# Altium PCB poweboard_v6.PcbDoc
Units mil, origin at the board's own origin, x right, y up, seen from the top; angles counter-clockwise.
Board outline 2952.84 x 1968.59 mil, 4 copper layers (Top Layer, Signal Layer 2, Signal Layer 1, Bottom Layer), stack 30.634 mil thick; 37 components, 25 nets, 129 pads, 118 vias.
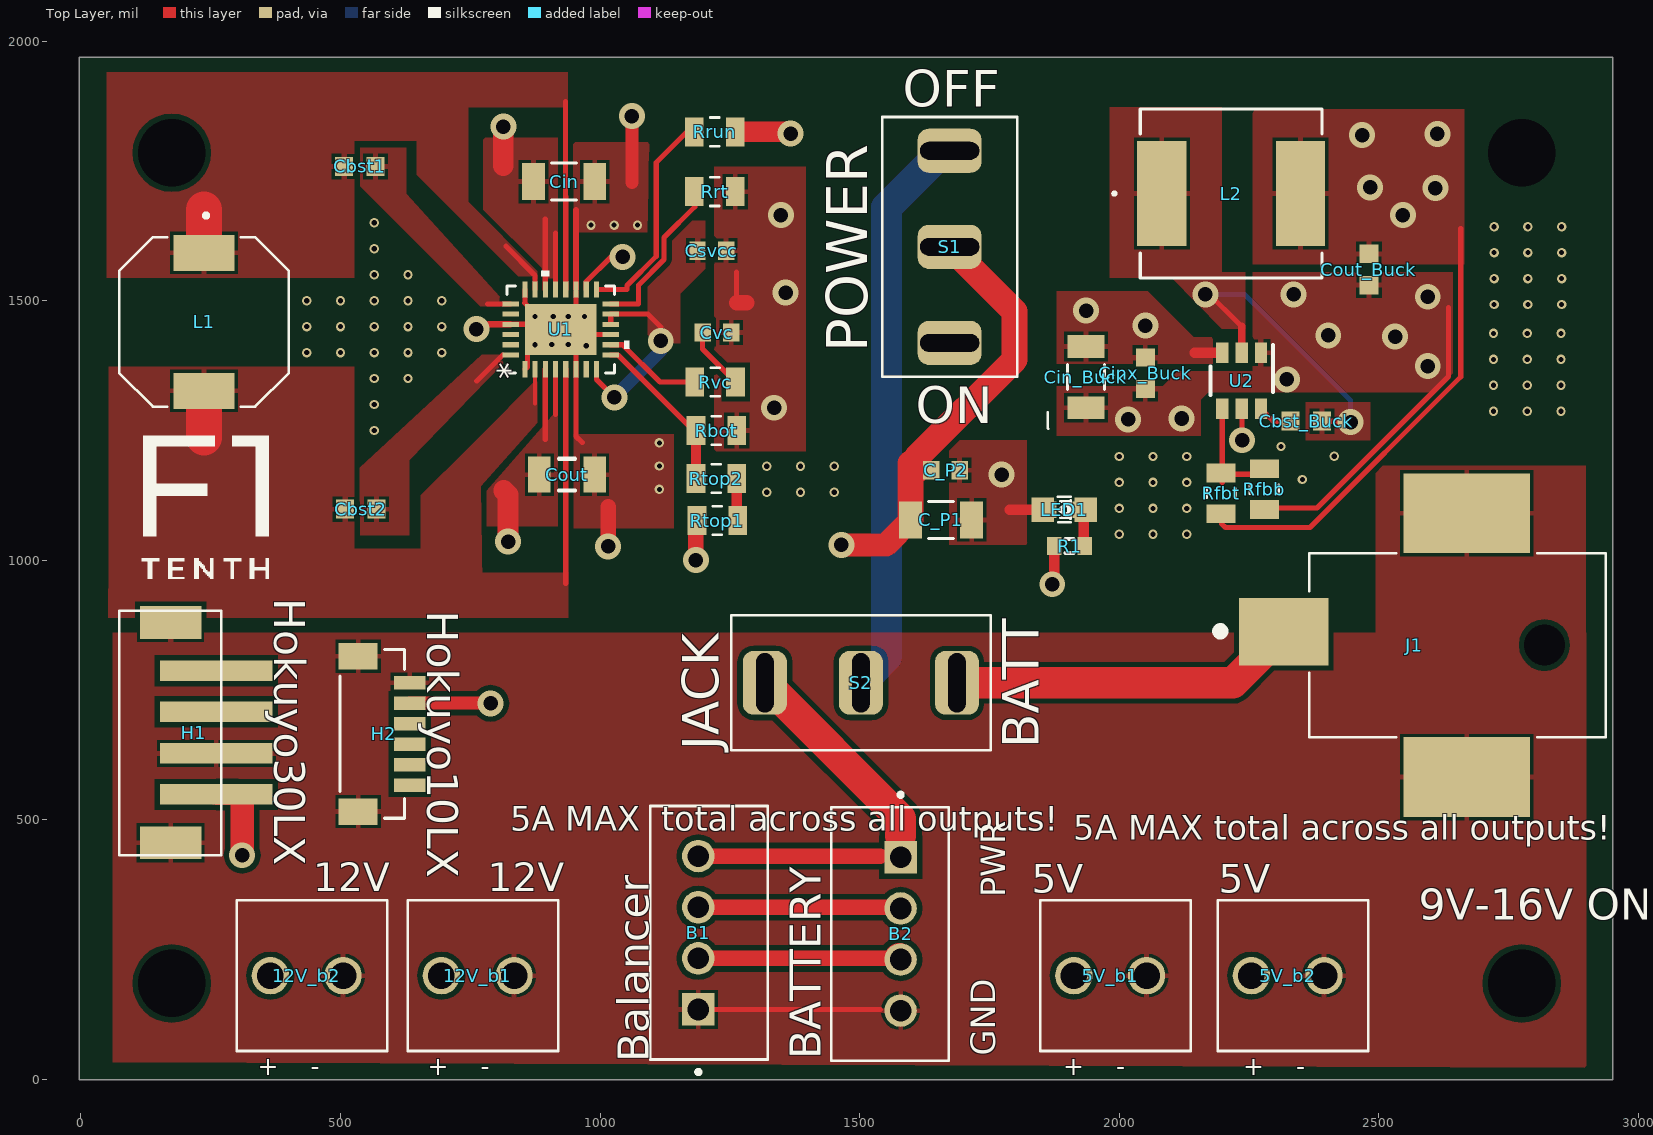
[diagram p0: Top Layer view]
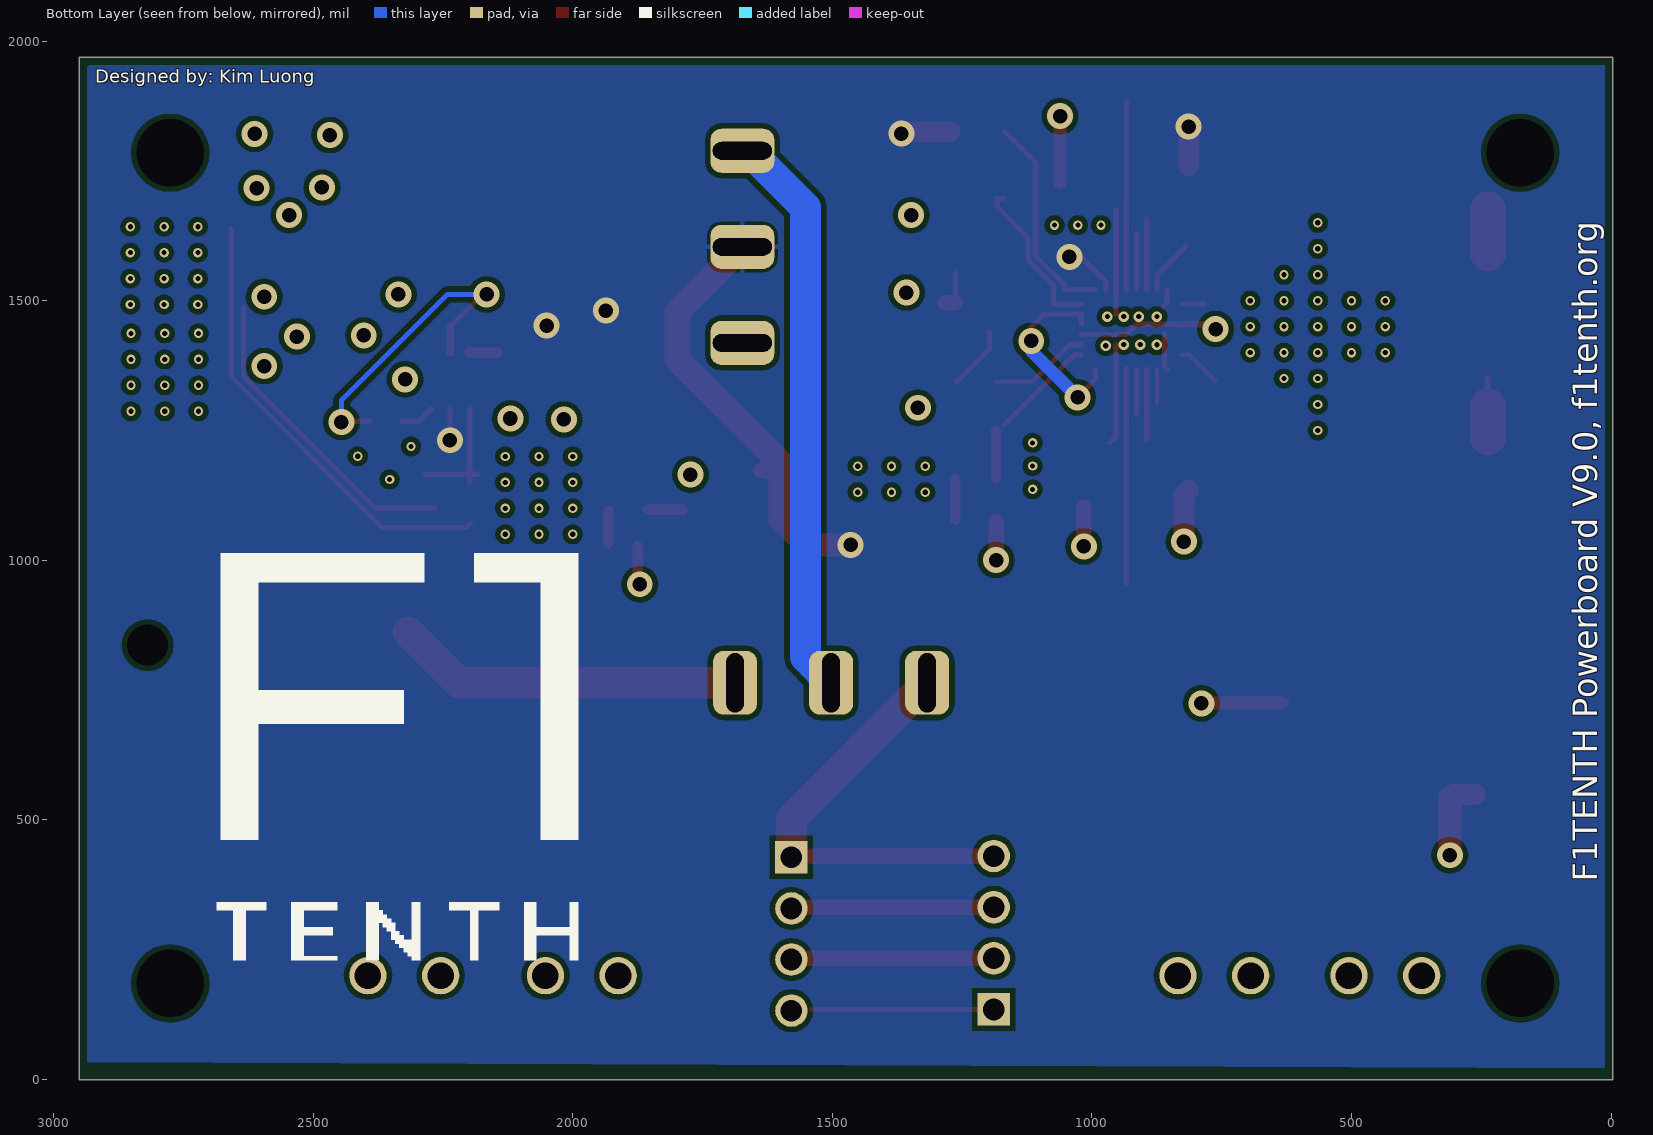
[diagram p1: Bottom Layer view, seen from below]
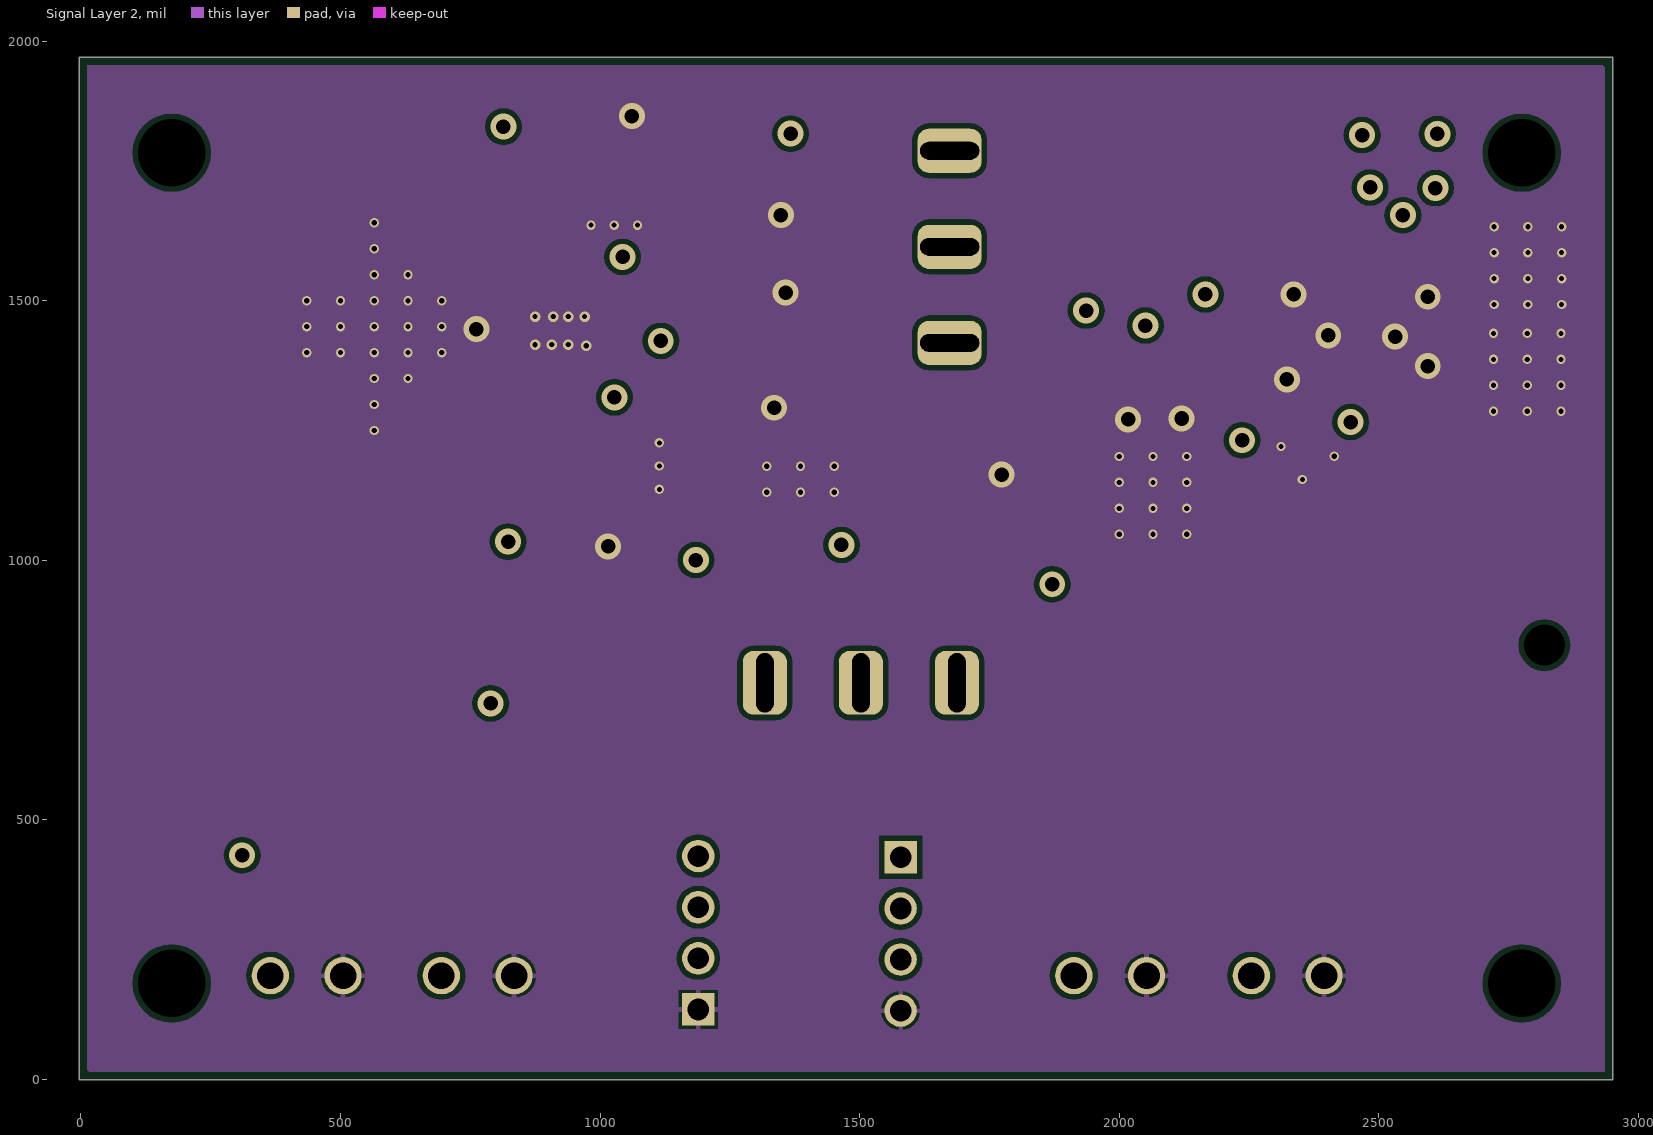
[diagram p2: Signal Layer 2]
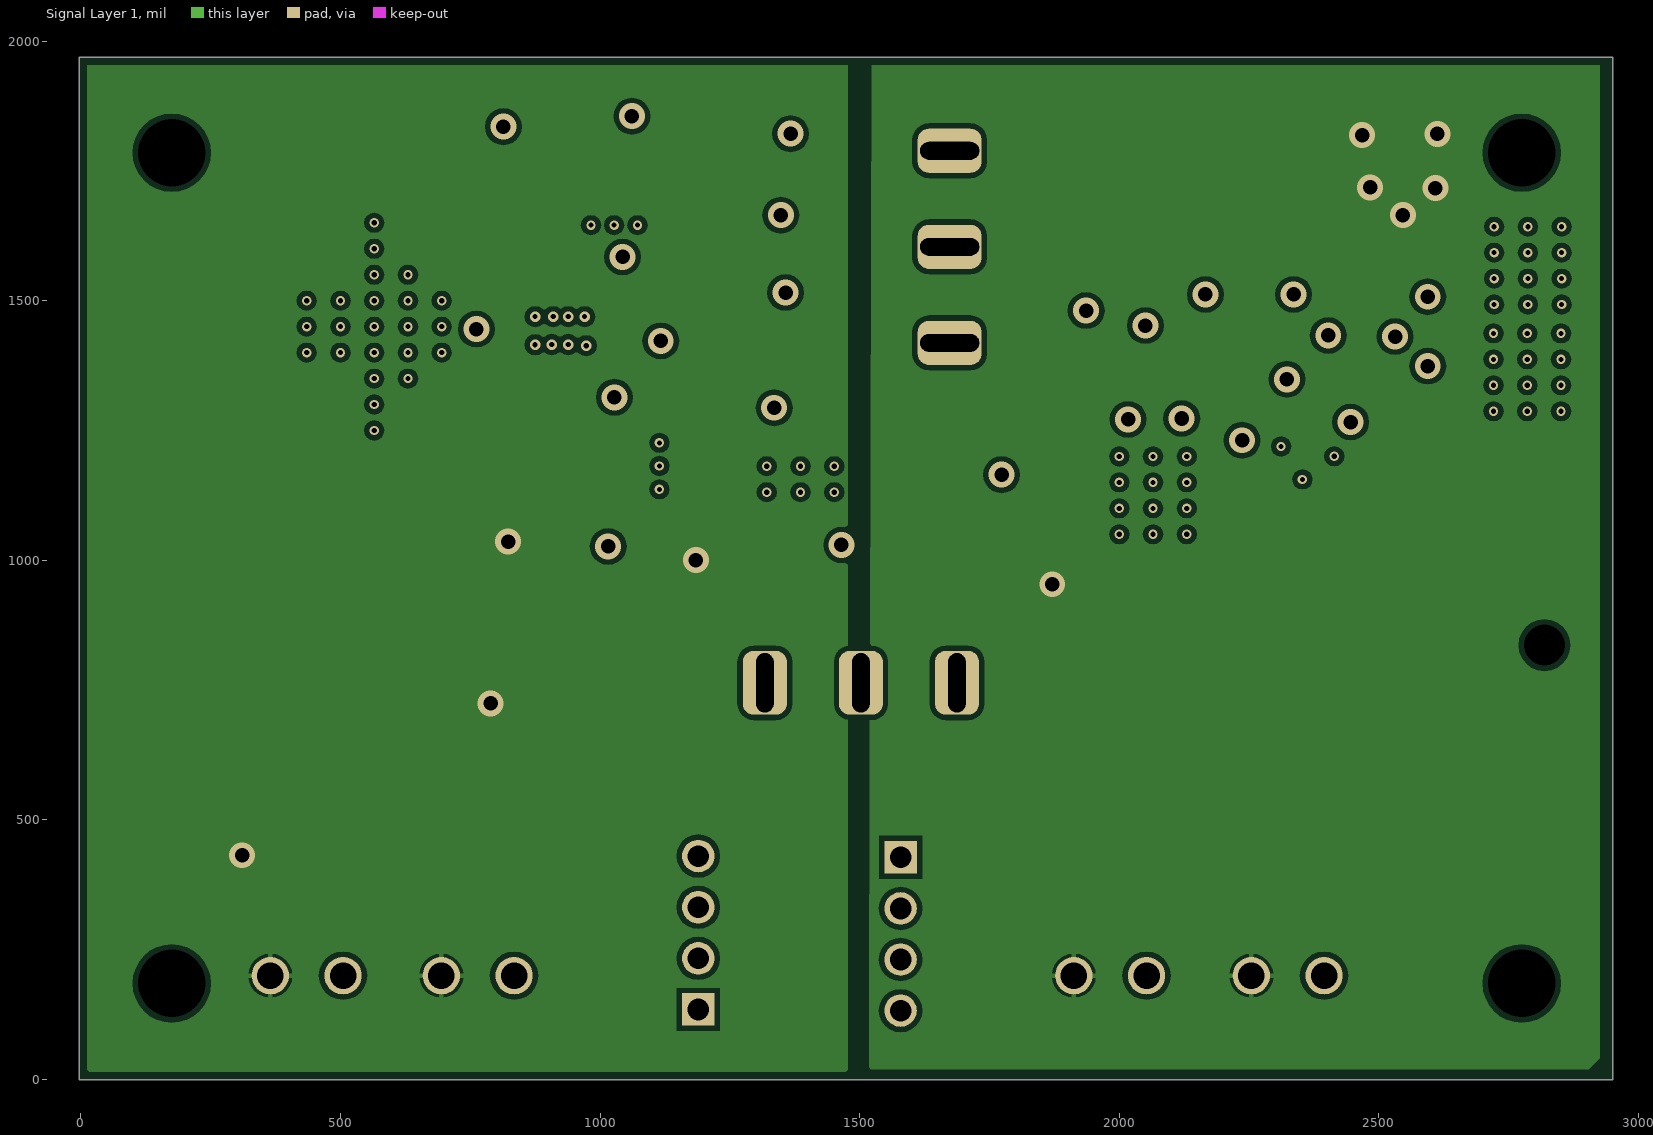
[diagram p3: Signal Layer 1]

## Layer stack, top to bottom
Top Solder: solder mask 0.4, Solder Resist, Dk 3.5
Top Layer: signal copper 1.4
Dielectric 1: core 10, FR-4, Dk 4.2
Signal Layer 2: signal copper 1.417
Dielectric 4: prepreg 5, Dk 4.2
Signal Layer 1: signal copper 1.417
Dielectric 3: core 10, Dk 4.2
Bottom Layer: signal copper 1.4
Bottom Solder: solder mask 0.4, Solder Resist, Dk 3.5

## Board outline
-2.76,-0.02 cw(c-2.76,0) -2.77,0 -2.77,1968.5 cw(c-2.76,1968.5) -2.76,1968.52 -2.76,1968.54 cw(c-2.72,1968.54) -2.72,1968.57 2950.04,1968.57 cw(c2950.04,1968.54) 2950.07,1968.54 2950.07,0.04 cw(c2950.04,0.04) 2950.04,0 2950.02,0 cw(c2950,0) 2950.02,0 cw(c2950,0) 2950,-0.02

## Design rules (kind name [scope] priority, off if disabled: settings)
BoardOutlineClearance [All] p1: gap=15 ignorepadtopadclearanceinfootprint=FALSE
Clearance "Clearance Polygons" [InPolygon] p1: gap=10 ignorepadtopadclearanceinfootprint=FALSE except(0: Arc-Hole Track-Hole SMDPad-Hole THPad-Hole Via-Hole Fill-Hole Poly-Hole Region-Hole Text-Hole)
Clearance [All] p2: gap=5 ignorepadtopadclearanceinfootprint=FALSE except(0: Arc-Hole Track-Hole SMDPad-Hole THPad-Hole Via-Hole Fill-Hole Poly-Hole Region-Hole Text-Hole)
ComponentClearance "HM-TRP & UFL" [InComponent('X1') vs InComponent('U1')] p1: gap=0 collisioncheckmode=3 verticalgap=0 showdistances=FALSE
ComponentClearance [All] p2: gap=1 collisioncheckmode=3 verticalgap=1 showdistances=FALSE
DiffPairsRouting [All] p1: maxlimit=393.7 minlimit=5 mostfreqgap=8 toplayer_minwidth=5 toplayer_maxwidth=15 toplayer_prefwidth=8 midlayer1_minwidth=5 midlayer1_maxwidth=15 midlayer1_prefwidth=8 midlayer2_minwidth=5 midlayer2_maxwidth=15 midlayer2_prefwidth=8 bottomlayer_minwidth=5 bottomlayer_maxwidth=15 bottomlayer_prefwidth=8 maxuncoupledlength=500
HoleSize [All] p1: absolutevalues=TRUE maxlimit=265 minlimit=10 maxpercent=80.000 minpercent=20.000
HoleToHoleClearance [All] p1: gap=10 allowstackedmicrovias=FALSE
MinimumAnnularRing [All] p1: minimumring=4
MinimumSolderMaskSliver [All] p1: minsoldermaskwidth=0
PlaneClearance [All] p1: clearance=10
PlaneConnect [All] p1: planeconnectstyle=Relief reliefexpansion=4 reliefentries=4 reliefconductorwidth=6 reliefairgap=6
PolygonConnect "Via connect style" [isVia] p1: connectstyle=Direct reliefconductorwidth=10 reliefentries=4 polygonreliefangle="90 Angle" airgapwidth=10
PolygonConnect [All] p2: connectstyle=Relief reliefconductorwidth=10 reliefentries=4 polygonreliefangle="90 Angle" airgapwidth=6
RoutingCorners [All] p1: cornerstyle=45-Degree minsetback=49.21 maxsetback=49.21
RoutingVias [All] p1: holewidth=12 width=22 viastyle="Through Hole" minholewidth=10 minwidth=18 maxholewidth=100 maxwidth=114
SilkToSilkClearance [All] p1: silktosilkclearance=0
SilkToSolderMaskClearance [IsPad] p1: minsilkscreentomaskgap=5 clearancetoexposedcopper=TRUE
SolderMaskExpansion [All] p1: expansion=2.5
Width GND [InNet('GND')] p1: maxlimit=30 minlimit=10 preferedwidth=20
Width Power [InNetClass('Power')] p2: maxlimit=40 minlimit=20 preferedwidth=30
Width 3V3 [InNetClass('3V3')] p3: maxlimit=30 minlimit=10 preferedwidth=20
Width [All] p4: maxlimit=400 minlimit=6 preferedwidth=8
20 further rules are at their usual default settings.

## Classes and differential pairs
component class Peripherals: B1 B2 C_P1 C_P2 H1 H2 J1 LED1 R1 S1 S2
component class TPS565201_Buck: 5V_b1 5V_b2 5Vout1 5Vout2 Buck Cbst_Buck Cin_Buck Cin_Buck_2 Cinx Cinx_Buck Cout_Buck Cout_Buck_2 L2 Rfbb Rfbt U2
component class LTC3119: 12V_b1 12V_b2 12Vout1 12Vout2 Cbst1 Cbst2 Cin Cout Csvcc Cvc L1 Rbot Rrt Rrun Rtop1 Rtop2 Rvc U1

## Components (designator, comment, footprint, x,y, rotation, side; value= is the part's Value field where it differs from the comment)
5V_b1 "EBWA-02-A" EBWA-02-A 1992.45,200 r0 top
5V_b2 "Part Number: 172310-1102" EBWA-02-A 2334.31,200 r0 top
12V_b1 "EBWA-02-A" EBWA-02-A 774.33,200 r0 top
12V_b2 "Part Number: 172310-1102" EBWA-02-A 444.99,200 r0 top
B1 "B4B-XH-A(LF)(SN)" *JST_B4B-XH-A(LF)(SN) 1189.16,135 r90 top value=Balancer
B2 "B4B-XH-A(LF)(SN)" *JST_B4B-XH-A(LF)(SN) 1578.84,428 r270 top value=Battery
C_P1 "Cap Semi" 1206_190 1656.59,1077.78 r180 top value=47uF
C_P2 "10uF" 1608[0603] 1665.43,1173.53 r180 top value=100nF
Cbst1 "Cap Sem" *CAPC1608X90N 537.34,1758.56 r180 top value=0.1uF
Cbst2 "0.1uF" *CAPC1608X90N 539.01,1098.35 r180 top value=.1uF
Cbst_Buck "100nF" *CAPC1608X90N 2360.12,1267.92 r0 top value=0.1uF
Cin "10uF" 1206_190 930.78,1729.37 r180 top value=Value
Cin_Buck "10uF" 1206_190 1935.82,1352.79 r270 top
Cinx_Buck "100nF" *CAPC1608X90N 2050.15,1360.24 r90 top value=0.1uF
Cout "47uF" 1206L 936.28,1165.03 r180 top locked value=Value
Cout_Buck "C1608X5R1A226M080AC" *CAPC1608X90N 2480.87,1559.93 r270 top value=22uF
Csvcc "Cap Semi" 1608[0603] 1215.28,1596.48 r180 top value=4.7uF
Cvc "Cap Semi" 1608[0603] 1225.13,1438.65 r0 top value=350pF
H1 "Hokuyo30LX" jst4pin 273.09,668.09 r90 top
H2 "Part Number: BM06B-SRSS-TB(LF)(SN)" CONN_BM06B-SRSS- 561.42,665.67 r270 top value=Value
J1 "Power Jack" CUI_PJ-036BH-SMT-TR 2316.72,862.15 r180 top locked
L1 "1.5uH" *IND_1217AS-H-1R5N=P3 237.35,1459.15 r270 top locked
L2 "IHLP3232DZER3R3M01" IHLP-3232DZ 2215.43,1706.38 r0 top value=3.3uH
LED1 "Power LED" WL-SMCW_0805 1894.32,1097.51 r0 top
R1 "Res3" J1-0603 1904.09,1027.5 r0 top value=600ohm
Rbot "Res3" *RESC2012X50N 1223.86,1249.88 r180 top value=97.6k
Rfbb "CRCW040210K0FKED" *RESC2012X50N 2279.2,1136.94 r270 top value=10k
Rfbt "CRCW040254K9FKED" *RESC2012X50N 2196.26,1128.9 r90 top value=54.9k
Rrt "Res3" *RESC2012X50N 1220.92,1709.98 r180 top value=34.8k
Rrun "Res3" *RESC2012X50N 1220.86,1825.2 r0 top value=100k
Rtop1 "Res3" *RESC2012X50N 1225.92,1076.53 r180 top value=1M
Rtop2 "Res3" *RESC2012X50N 1224.03,1157.5 r0 top value=374k
Rvc "Res3" *RESC2012X50N 1221.75,1343.34 r180 top value=155k
S1 "E101MD1AQE" E101MD1AQE 1543.26,1353.71 r0 top
S2 "E101MD1AQE" E101MD1AQE 1752.37,634.1 r90 top
U1 "LTC3119EUFD#PBF" QFN28_UFD 924.12,1444.64 r90 top locked value=Value
U2 "TPS565201DDCR" DDC0006A_N 2235.66,1345.6 r270 top value=Value

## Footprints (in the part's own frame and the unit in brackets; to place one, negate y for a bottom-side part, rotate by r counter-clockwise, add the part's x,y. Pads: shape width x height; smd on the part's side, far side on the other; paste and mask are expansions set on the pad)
1206_190 [mil]
  rect 44x71 smd: 1(-59,0) 2(59,0)
  silkscreen extent -24,-36 24,36
1206L [mm]
  rect 1.1x1.75 smd paste+0 mask+0.051: 1(-1.35,0) 2(1.35,0)
  silkscreen extent -0.4,-0.77 0.4,0.77
1608[0603] [mm] "Chip Capacitor, Body 1.6x0.8mm, IPC High Density"
  rect 0.8x0.9 smd: 1(-0.7,0) 2(0.7,0)
  body extent -0.87,-0.48 0.87,0.48, height 1.3
*CAPC1608X90N [mm]
  rect 0.89x0.93 smd: 1(-0.77,0) 2(0.77,0)
*IND_1217AS-H-1R5N=P3 [mm]
  rect 1.75x3 smd: 1(-3.375,0) 2(3.375,0)
  silkscreen extent -5.3,-4.15 4.15,4.15
*JST_B4B-XH-A(LF)(SN) [mm]
  rect 1.59x1.59 hole 1.06: 1(0,0)
  round 1.59 hole 1.06: 2(2.5,0) 3(5,0) 4(7.5,0)
  silkscreen extent -3.16,-3.4 9.95,2.35
*RESC2012X50N [mm]
  rect 0.92x1.42 smd: 1(-1,0) 2(1,0)
  silkscreen extent -0.22,-0.7 0.22,0.7
CONN_BM06B-SRSS- [mil]
  rect 26x61 smd paste+0 mask+0: 1(-98.43,72.04) 2(-59.06,72.04) 3(-19.68,72.04) 4(19.68,72.04) 5(59.06,72.04) 6(98.43,72.04)
  rect 51x75 smd: 7(-149.61,-27.37) 8(149.61,-27.37)
  silkscreen extent -162,-62 162,62, body extent 0,0 10,10, height 10
CUI_PJ-036BH-SMT-TR [mm]
  rect 4.4x3.3 smd: 1(0,0)
  rect 6.2x3.9 smd: 2(-8.95,7.1) 3(-8.95,-5.8)
  round 0 hole 2 unplated: ""(-12.75,0.65)
  silkscreen extent -15.75,-3.85 3.3,5.15
DDC0006A_N [mm]
  rect 1x0.6 smd paste+0 mask+0.051: 1(-1.375,0.95) 2(-1.375,0) 3(-1.375,-0.95) 4(1.375,-0.95) 5(1.375,0) 6(1.375,0.95)
  silkscreen extent -1.75,-1.52 0.7,1.53
E101MD1AQE [mil] "SWITCH TOGGLE SPDT 7.5A 125V"
  rrect50% 123x85 hole 34 slot 114 at 0 deg: 1(130,435) 2(130,250) 3(130,65)
  silkscreen extent 0,0 260,500
EBWA-02-A [mil]
  round 72 hole 51: 1(-80,0) 2(60,0)
  silkscreen extent -145,-145 145,145
IHLP-3232DZ [mil]
  rect 95x203 smd: 1(-133.5,0) 2(133.5,0)
  silkscreen extent -228,-163 175,162
J1-0603 [mm] "Chip Resistor, Body 1.6x0.8mm, IPC High Density"
  rect 0.7x0.9 smd: 1(-0.75,0) 2(0.75,0)
  silkscreen extent -0.2,-0.35 0.2,0.35, body extent -0.85,-0.48 0.85,0.48, height 0.9
jst4pin [mm]
  rect 1x5.5 smd: 1(-3.023,0.305) 2(-1.016,0.305) 3(1.016,0.305) 4(3.023,0.305)
  rect 1.6x3 smd: 5(-5.385,2.54) 6(5.385,2.54)
  silkscreen extent -6,0.06 5.97,5.06
QFN28_UFD [mm]
  rect 0.805x0.25 smd: 1(-1.952,1.75) 2(-1.952,1.25) 3(-1.952,0.75) 4(-1.952,0.25) 5(-1.952,-0.25) 6(-1.952,-0.75) 7(-1.952,-1.25) 8(-1.952,-1.75) 15(1.952,-1.75) 16(1.952,-1.25) 17(1.952,-0.75) 18(1.952,-0.25) 19(1.952,0.25) 20(1.952,0.75) 21(1.952,1.25) 22(1.952,1.75)
  rect 0.25x0.805 smd: 9(-1.25,-2.452) 10(-0.75,-2.452) 11(-0.25,-2.452) 12(0.25,-2.452) 13(0.75,-2.452) 14(1.25,-2.452) 23(1.25,2.452) 24(0.75,2.452) 25(0.25,2.452) 26(-0.25,2.452) 27(-0.75,2.452) 28(-1.25,2.452)
  rect 2.5x3.5 smd paste+0 mask+0: 29(0,0)
  silkscreen extent -2.13,-3.36 2.86,2.63
WL-SMCW_0805 [mm]
  rect 1.1x1.2 smd: 1(-1.05,0) 2(1.05,0)
  rect 0.8x0.8 smd: 1(-0.8,0) 2(0.8,0)
  silkscreen extent -0.31,-0.62 0.32,0.63

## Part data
5V_b2 12V_b2: library part EBWA-02-A
B1 B2: "Connector Header Through Hole 4 position 0.098 _2.50mm_", Package=None
C_P1 Cin Cout: library part TCJY106M035R0070, "No Description Available"
C_P2 Cbst1 Cbst2 Cbst_Buck Cinx_Buck: library part GRM188R61E104KA01D, "SMD Capacitor X5R_EIA_ with Capacitance: 0.10uF Tol. 10%. Rated Voltage: 25Vdc", Package="1608 Murata"
Cin_Buck: library part GRM31CR61E106KA1, "Imported", Manufacturer_Name=MuRata, Manufacturer_Part_Number=GRM31CR61E106KA12L
Cout_Buck: "C1608X5R1A226M08", Manufacturer Name=TDK
Csvcc Cvc: "Capacitor (Semiconductor SIM Model)"
H1: library part Component_1
H2: library part BM06B-SRSS-TB(LF, "No Description Available", Manufacturer_Part_Number=BM06B-SRSS-TB(LF)(SN)
J1: library part PJ-036BH-SMT-TR, "2.5 x 6.3 mm, 5.0 A, Horizontal, Surface Mount _SMT_, Dc Power Jack Connector", Package=None
L1: library part 1217AS-H-1R5N=P3, "Inductor with Inductance: 1.5uH Tol. +/-30%, Package: 3131 _8080_", Package=NONSTANDARD
L2: library part L1, "Unknown", Manufacturer Name=Vishay-Dale
LED1: library part WL-SMCW, "Green 520nm LED Indication - Discrete 3.2V 0805 _2012 Metric_", Package="0805 Würth Elektronik"
R1 Rbot Rrt Rrun Rtop1 Rtop2 Rvc: "Resistor"
Rfbb: library part Rfbb, Manufacturer Name=Vishay-Dale
Rfbt: library part Rfbt, Manufacturer Name=Vishay-Dale
S1 S2: "C&K SWITCH TOGGLE SPDT 7.5A 125V"
U1: "No Description Available"
U2: "Imported", Manufacturer="Texas Instruments"

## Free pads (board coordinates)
  round 0 hole 130 unplated: 2(175,185) 2(175,1785) 2(2775,185) 2(2775,1785)

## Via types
v1: diameter 18, hole 10, Top Layer to Bottom Layer, tented both sides, 74 vias
v2: diameter 50, hole 28, Top Layer to Bottom Layer, tented both sides, 36 vias
v3: diameter 20, hole 10, Top Layer to Bottom Layer, tented bottom, 8 vias

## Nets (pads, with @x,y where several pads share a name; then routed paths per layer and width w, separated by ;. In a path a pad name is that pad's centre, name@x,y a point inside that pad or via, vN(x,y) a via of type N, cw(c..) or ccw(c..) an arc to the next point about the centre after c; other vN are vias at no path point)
5Vout: 5V_b1.1 5V_b2.1 Cout_Buck.1 L2.2 R1.1 Rfbt.1 | length 944.4
  Top Layer w10: 2197.22,1070.22 2204.39,1063.05 2367.33,1063.05 2657.76,1353.47 2657.76,1638.88
  Top Layer w20: v2(1870.85,953.86) 1874.56,957.56 R1.1
  other v2: 2546.02,1664.58 2608.9,1716.76 2483.07,1718.16 2467.78,1818.8 2612.44,1821.22
12Vout: 12V_b1.1 12V_b2.1 Cout.2 H1.1 H2.2 Rtop1.2 U1.3 U1.4 | length 719.4
  Top Layer w10: 894.6,1232.39 U1.3 ; 914.28,1281.32 U1.4 ; Rtop1.2@1184.49,1074.47 Rtop1.2
  Top Layer w25: H2.2 v2@789.19,724.73
  Top Layer w30: v2@789.19,724.73 v2(789.37,724.55) ; v2(1184.49,1000.5) Rtop1.2@1184.49,1074.47
  Top Layer w40: H1.1 303.49,549.09 H1.1@310.82,541.76 ; 814.39,1134.52 822.78,1126.13 v2(822.78,1035.8)
  Top Layer w45: v2(310.82,431.99) H1.1@310.82,541.76
GND: 5V_b1.2 5V_b2.2 12V_b1.2 12V_b2.2 B1.1 B2.4 C_P1.1 C_P2.1 Cin.1 Cin_Buck.2 Cinx_Buck.1 Cout.1 Cout_Buck.2 Csvcc.1 Cvc.2 H1.2 H1.5 H1.6 H2.1 H2.7 H2.8 J1.2 J1.3 LED1.1 Rbot.1 Rfbb.2 Rrt.1 U1.1 U1.6 U1.11 U1.17 U1.22 U1.25 U1.29 U2.1 | length 2086.3
  Top Layer w10: v2(761.73,1445.24) 775.68,1445.24 v2@784.93,1454.48 ; U1.25 914.28,1454.48 U1.29 933.97,1434.8 U1.11 ; U1.1 859.99,1372.54 U1.29@859.99,1436.67 ; U1.22 855.23,1495.66 855.12,1495.66 U1.29@862.49,1488.29 ; U1.29@953.65,1415.11 U1.6 953.65,1238.49 965.53,1226.61 ; U1.29@953.65,1474.17 U1.17 ; B1.1 1539.67,135 ; 1262.73,1555.44 1262.73,1495.34 1263.4,1496.01 ; LED1.1@1852.98,1097.51 LED1.1@1862.82,1097.51 ; Rfbb.2@2265.7,1100.93 2380.66,1100.93 2633.86,1354.13 2633.86,1487.06
  Top Layer w11: U1.17 953.65,1674.45
  Top Layer w12: v2@784.93,1454.48 U1.25
  Top Layer w20: 1789.36,1097.51 LED1.1@1852.98,1097.51
  Top Layer w25: 1061.36,1727.25 v2(1061.36,1855.25)
  Top Layer w30: v2(1015.68,1026.66) 1015.68,1103.49 ; 1263.4,1496.01 1281.96,1496.01
  other v1: 2000,1050 2065,1050 2130,1050 2000,1100 2065,1100 2130,1100 1321.07,1131.24 1386.07,1131.24 1451.07,1131.24 1114.31,1136.65 2000,1150 2065,1150 2130,1150 2352.6,1155.75 1321.07,1181.24 1386.07,1181.24 1451.07,1181.24 1114.31,1181.69 2000,1200 2065,1200 2130,1200 2413.95,1200.31 2311.55,1219.2 1114.31,1226.15 565,1250 2720.64,1286.96 2785.64,1286.96 2850.64,1286.96 565,1300 2720.64,1336.96 2785.64,1336.96 2850.64,1336.96 565,1350 630,1350 2720.64,1386.96 2785.64,1386.96 2850.64,1386.96 435,1400 500,1400 565,1400 630,1400 695,1400 2720.64,1436.96 2785.64,1436.96 2850.64,1436.96 435,1450 500,1450 565,1450 630,1450 695,1450 2721.9,1492.56 2786.9,1492.56 2851.9,1492.56 435,1500 500,1500 565,1500 630,1500 695,1500 2721.9,1542.56 2786.9,1542.56 2851.9,1542.56 565,1550 630,1550 2721.9,1592.56 2786.9,1592.56 2851.9,1592.56 565,1600 2721.9,1642.56 2786.9,1642.56 2851.9,1642.56 982.54,1645.48 1027.01,1645.48 1072.04,1645.48 565,1650
  other v2: 1773.21,1164.89 2016.97,1271.39 2120.14,1273.09 1335.42,1293.79 2322.92,1348.63 2594.03,1373.93 2531.16,1430.95 2402.43,1433.01 2594.03,1507.55 2335.66,1512.12 1357.2,1515.55 1348.06,1664.58
  other v3: 973.34,1413.37 874.91,1415.11 907.06,1415.5 938.85,1415.5 874.91,1469.37 909.91,1469.37 938.85,1469.37 970.19,1469.37
N/C: S1.3
NetB1_2: B1.2 B2.3 | length 390.6
  Top Layer w30: B1.2 B2.3@1576.56,233.43
  Top Layer w60: B2.3@1576.56,233.43 B2.3
NetB1_3: B1.3 B2.2 | length 389.7
  Top Layer w30: B1.3 B2.2@1578.84,331.85
NetCbst1_1: Cbst1.1 U1.23 | length 44
  Top Layer w10: 783.58,1493.85 U1.23
NetCbst1_2: Cbst1.2 L1.1 U1.18 U1.21 | length 564.3
  Top Layer w10: 818.63,1604.95 874.91,1548.67 U1.21 ; 933.33,1883.86 U1.18
  Top Layer w40: L1.1 237.35,1580.61 L1.1@237.66,1580.61
  Top Layer w70: L1.1 237.35,1675.44
NetCbst2_1: Cbst2.1 U1.28 | length 85.7
  Top Layer w8: U1.28@812.57,1395.43 U1.28
  Top Layer w10: 762.56,1345.41 U1.28@812.57,1395.43
NetCbst2_2: Cbst2.2 L1.2 U1.2 U1.5 | length 623.7
  Top Layer w8: 874.91,1302.02 U1.2
  Top Layer w10: L1.2 237.35,1296.57 237.66,1296.88 L1.2@237.66,1352.39 ; 933.97,955.44 U1.5
  Top Layer w70: 237.35,1236.58 L1.2@237.35,1296.57
NetCbst_Buck_1: Cbst_Buck.1 U2.6 | length 66.5
  Top Layer w10: U2.6 2296.6,1267.92 Cbst_Buck.1
NetCbst_Buck_2: Cbst_Buck.2 L2.1 U2.2 | length 619.2
  Top Layer w10: v2(2165.69,1512.12) 2165.69,1520.07 2235.66,1450.1 ; Cbst_Buck.2 2443.94,1267.92 v2(2445.54,1266.32)
  Top Layer w15: U2.2 2235.66,1450.1
  Bottom Layer w10: v2(2165.69,1512.12) 2241.56,1512.12 2445.54,1308.14 v2(2445.54,1266.32)
NetCsvcc_2: Csvcc.2 U1.8 U1.12 U1.13 | length 366.7
  Top Layer w10: U1.8 993.02,1348.44 v2(1027.55,1313.91) ; U1.12 U1.13 1091.93,1474.17 1116.89,1449.2 v2(1116.89,1422.61)
  Bottom Layer w25: v2(1027.55,1313.91) 1116.89,1403.25 v2(1116.89,1422.61)
NetCvc_1: Cvc.1 Rvc.1 | length 121.6
  Top Layer w10: Cvc.1 1197.57,1406.89 Rvc.1
NetLED1_2: LED1.2 R1.2 | length 62.2
  Top Layer w20: R1.2@1931.79,1033 LED1.2@1931.79,1095.21
NetRbot_2: Rbot.2 Rtop2.1 U1.9 | length 298.4
  Top Layer w10: U1.9 1034.55,1395.43 Rbot.2@1170.35,1259.62 ; Rbot.2 Rbot.2@1184.66,1249.71
  Top Layer w20: Rtop2.1 Rbot.2@1184.66,1249.71
NetRfbb_1: Rfbb.1 Rfbt.2 U2.4 | length 243
  Top Layer w10: Rfbt.2@2182.37,1165.88 Rfbt.2@2198.26,1165.88 ; 2198.26,1149.99 Rfbt.2@2198.26,1165.88 ; U2.4 Rfbt.2@2198.26,1165.88 ; Rfbb.1@2283.92,1165.88 Rfbt.2@2198.26,1165.88
NetRrt_2: Rrt.2 U1.14 | length 312.9
  Top Layer w10: U1.14 1073.74,1493.85 1073.74,1529.87 1123.36,1579.49 1123.36,1621.83 1182.38,1680.85 1182.38,1696.51 Rrt.2@1170.23,1696.51
NetRrun_1: Rrun.1 U1.15 | length 410.4
  Top Layer w10: U1.15@993.26,1521.51 1052.05,1521.51 1052.05,1529.4 1108.36,1585.7 1108.36,1765.84 Rrun.1@1167.72,1825.2
NetRtop1_1: Rtop1.1 Rtop2.2 | length 79.1
  Top Layer w20: Rtop1.1@1263.4,1078.42 Rtop2.2
NetRvc_2: Rvc.2 U1.10 | length 191.4
  Top Layer w10: U1.10 1043.4,1415.11 1115.17,1343.34 Rvc.2
PWR_SRC: S1.1 S2.2 | length 1080.3
  Bottom Layer w60: S2.2 1551.83,813.56 1551.83,1679.53 S1.1@1653.91,1781.6
Vbatt: B1.4 B2.1 S2.1 | length 753.5
  Top Layer w30: B1.4 1539.67,430.28
  Top Layer w60: S2.1 1578.84,502.63 1578.84,469.44
Vin: C_P1.2 C_P2.2 Cin.2 Cin_Buck.1 Cinx_Buck.2 Rrun.2 S1.2 U1.16 U1.19 U1.20 U2.3 U2.5 | length 1473.1
  Top Layer w10: U1.20 894.6,1657.25 ; U1.19 914.28,1630.39 ; U1.16 973.34,1536.73 1020.8,1584.19 v2(1043.4,1584.19) ; U2.5 2236.42,1290.7 v2(2236.42,1231.19)
  Top Layer w20: 2145.26,1399.74 U2.3
  Top Layer w30: C_P1.2@1597.59,1076.53 C_P1.2 ; 1610.11,1173.53 C_P2.2
  Top Layer w40: 813.77,1759.74 v2(813.77,1835.09) ; Rrun.2@1274.01,1825.2 1363.3,1825.2 v2(1366.94,1821.57)
  Top Layer w45: v2(1464.77,1029.52) 1550.57,1029.52 C_P1.2@1597.59,1076.53
  Top Layer w50: C_P1.2 1597.59,1186.06 1610.11,1173.53 ; 1611.46,1199.94 1798.17,1386.65 1798.17,1478.8 S1.2
  other v2: 2050.15,1452.04 1936.24,1480.83
Vjack: J1.1 S2.3 | length 670
  Top Layer w60: S2.3 2218.67,764.1 J1.1
pads on no net: H1.3 H1.4 H2.3 H2.4 H2.5 H2.6 J1. U1.7 U1.24 U1.26 U1.27

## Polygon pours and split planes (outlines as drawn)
GND on Signal Layer 2 "GND" (solid, pour order 32): -2.76,0 2950,0 2950,1968.5 -2.76,1968.5
5Vout on Signal Layer 1 "Signal Layer 1-5Vout" (solid, pour order 97): 1523.09,1953.21 1525.86,1955.98 2925.05,1955.98 2925.05,40.76 2904.01,19.71 1517.95,19.71
12Vout on Signal Layer 1 "Signal Layer 1-12Vout" (solid, pour order 37): 3.55,1968.29 1476.54,1968.29 1476.54,3.37 -2.07,3.37
GND on Top Layer "Top Layer-GND 4" (solid, pour order 123): 61.28,32.88 61.28,860.59 2899.29,860.59 2899.29,23.16
GND on Top Layer "Top Layer-GND 6" (solid, pour order 133): 1672.33,1231.14 1672.33,1029.52 1827.22,1029.52 1822.18,1034.56 1822.18,1231.14
NetCbst1_1 on Top Layer "Top Layer-NetCbst1_2" (solid, pour order 83): 537.95,1794.73 537.95,1720.59 769.47,1489.06 823.27,1489.06 626.95,1706.38 626.95,1794.73
NetCbst2_1 on Top Layer "Top Layer-NetCbst2_1" (solid, pour order 45): 537.64,1178.3 537.92,1047.85 632.3,1047.85 632.3,1192.88 828.89,1395.43 771.99,1395.43
NetCsvcc_2 on Top Layer "Top Layer-No Net 1" (solid, pour order 129): 1091.93,1434.8 1108.83,1417.9 1154.46,1417.9 1154.46,1513.31 1202.25,1561.09 1202.25,1654.33 1177.22,1654.33 1091.93,1569.04
GND on Top Layer "Top Layer-No Net 2" (solid, pour order 125): 2898.76,694.55 2898.76,1181.69 2494.03,1181.69 2494.03,694.55
GND on Top Layer "Top Layer-GND 5" (solid, pour order 119): -2.76,459.14
Vin on Top Layer "Top Layer-Vin 1" (solid, pour order 109): 1879.18,1518.27 1879.18,1378.45 2216.17,1378.45 2220.07,1382.34 2213.61,1388.8 2213.61,1429.42 2143.5,1429.42 2054.65,1518.27
NetCbst_Buck_2 on Top Layer "Top Layer-NetCbst_2" (solid, pour order 107): 2365.65,1304.11 2359.17,1304.11 2359.17,1231.19 2483.35,1231.19 2483.35,1304.11
NetCbst_Buck_2 on Top Layer "Top Layer-NetCbst_2 1" (solid, pour order 105): 1981.6,1872.39 1981.6,1543.88 2101.46,1543.88 2197.22,1445.68 2242.55,1445.68 2242.55,1554.85 2197.22,1554.85 2197.22,1872.39
GND on Top Layer "Top Layer-GND 3" (solid, pour order 103): 2648.55,1554.57 2257.23,1554.57 2257.23,1364.26 2112.86,1364.26 2084.02,1335.42 1879.18,1335.42 1879.18,1239.57 2156.59,1239.57 2156.59,1308.86 2174.78,1327.05 2177.88,1323.95 2343.09,1323.95 2648.55,1323.95
5Vout on Top Layer "Top Layer-5Vout" (solid, pour order 101): 2260.48,1868.88 2257.4,1860.95 2257.4,1569.97 2664.08,1569.97 2664.08,1868.88
GND on Top Layer "Top Layer-GND" (solid, pour order 93): 1219.99,1758.05 1395.72,1758.05 1395.72,1210.47 1219.82,1210.47
Vin on Top Layer "Top Layer-Vin" (solid, pour order 91): 775.09,1813.84 775.09,1656.93 896.96,1535.06 927.49,1535.06 920.86,1813.84
GND on Top Layer "Top Layer-GND 1" (solid, pour order 89): 1094.93,1804.88 1091.24,1631.78 947.08,1631.78 946.83,1804.88 1011.73,1804.88
NetCbst1_2 on Top Layer "Top Layer-NetCbst1_1 1" (solid, pour order 85): 49.46,1939.53 938.2,1939.53 938.2,1872.9 922.73,1872.9 49.46,1870.58
12Vout on Top Layer "Top Layer-12Vout" (solid, pour order 77): 781.34,1133.72 782.09,1065.67 933.89,1065.67 931.71,1305.43
GND on Top Layer "Top Layer-GND 2" (solid, pour order 71): 947.04,1242.75 946.13,1061.53 1141.77,1061.53 1141.77,1242.75 993.36,1242.75
NetCbst1_2 on Top Layer "Top Layer-NetCbst1_1" (solid, pour order 63): 50.14,1643.95 50.14,1544.07 526.39,1544.07 526.39,1808.08 647.16,1808.08 647.16,1742.47 876.3,1513.33 892.08,1529.11 892.08,1544.07 746.04,1690.11 746.04,1898.68 50.14,1898.68
NetCbst2_2 on Top Layer "Top Layer-NetCbst2_2" (solid, pour order 49): 742.18,888.98 938.85,888.98 938.85,976.27 742.18,976.27
NetCbst2_2 on Top Layer "Top Layer-NetCbst2_2 2" (solid, pour order 39): 53.89,1372.42 526.39,1372.42 526.39,1022.73 655.05,1022.73 655.05,1125.11 747.84,1217.89 773.77,1243.83 883.13,1353.76 883.13,1269.51 770.69,1142.87 773.77,888.98 52.59,888.98 52.59,945.26 53.89,946.57
Vin on Bottom Layer "Bottom Layer-Vin" (solid, pour order 111): -2.68,1968.5 2950,1968.5 2950,33.2 3.38,21.28

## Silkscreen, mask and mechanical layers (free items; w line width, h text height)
Top Overlay:
  drawing of 9 lines, arcs and shapes, not listed
  text "POWER" at 1514.84,1400.27 h78.74 r90
  text "Hokuyo10LX" at 666.97,903.32 h60 r270
  text "5A MAX  total across all outputs!" at 826.82,478.82 h47.24
  text "5A MAX total across all outputs!" at 1911.53,461.76 h47.24
  text "12V" at 447.59,362.51 h55
  text "12V" at 783.94,362.66 h55
  text "5V" at 1830.92,359.99 h55
  text "5V" at 2191.49,359.99 h55
  text "PWR" at 1780.34,351.3 h47.24 r90
  text "9V-16V ONLY" at 2576.25,307.98 h60
  text "GND" at 1760.67,45.99 h47.24 r90
  text "BATTERY" at 1425,38.82 h60 r90
  text "Balancer" at 1093.81,33.48 h60 r90
  text "+    -" at 341.09,7.97 h35
  text "+    -" at 668.09,7.97 h35
  text "+    -" at 1892.02,7.97 h35
  text "+    -" at 2238.76,7.97 h35
Bottom Overlay:
  drawing of 7 lines, arcs and shapes, not listed
  text "Designed by: Kim Luong" at 2919.32,1920.17 h25
  text "F1TENTH Powerboard V9.0, f1tenth.org" at 27.25,381.32 h47.24 r270
Mechanical 1:
  lines w10: -2.76,0 2950,0 2950,1968.5 -2.76,1968.5 -2.76,0 ; -2.72,0.04 2950.04,0.04 2950.04,1968.54 -2.72,1968.54 -2.72,0.04
Mechanical 5:
  circle w0.04: c2773.66,1784.29 r65
  circle w0.04: c2773.66,184.29 r65
  circle w0.04: c173.66,1784.29 r65
  circle w0.04: c173.66,184.29 r65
